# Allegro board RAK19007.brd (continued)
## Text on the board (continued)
User.Comments: 1 | 2 | 3 | 4 | B1 | C1 | G1 | J1 | L1 | N1 | R1 | U1 | W1 | D2 | F2 | H2 | K2 | M2 | P2 | T2 | Y2 | AB2 | AD2 | B3 | AD4 | B5 | AC5 | AD6 | B7 | A8 | AD8 | B9 | AC9 | A10 | AD10 | B11 | AC11 | A12 | AD12 | B13 | DPAD | AC13 | A14 | AD14 | B15 | AC15 | A16 | AD16 | B17 | AC17 | A18 | AD18 | B19 | AC19 | A20 | AD20 | AC21 | A22 | AD22 | A23 | D23 | F23 | H23 | P23 | T23 | V23 | Y23 | AD23 | B24 | E24 | J24 | L24 | N24 | R24 | U24 | W24 | AA24 | AC24 | USB-MC-001-05 | CM212H | PH254-115-04 | 8 | 7 | 9 | 6 | 5
Ref Des/Assembly Top: 4PIN | MICRO_USB_NJZ_MICRO_USB_001_4PI | 32.768K | CM212H_CM212H_32.768K_CM212H | HEADER1X4_PH254-115-04_HEADER1X | Header1X4 | J5 | X1 | J9 | J14 | J15 | J10 | J12 | U10
Ref Des/Silkscreen Top: CPU SLOT | SLOT B | SLOT A | IO SLOT | RESET | SOLAR | BATTERY | RAK19007 Ver.C
BODY_CENTER: OPEN WINDOW | V-cut | 4842.5180 mil | 4409.4460 mil
DIMENSION: SOLDER MASK:BLACK | BOARD NAME: | UNITS:      MILS | SILKSCREEN COLOR: WHITE | DIELECTRIC MATERIAL: FR-4 | PLATED TECHNICS: | SINGLE IMPEDANCE | DIFF IMPEDANCE | SHORT NET NO. | REQUIREMENT. | [Zo] | [0] | RAK19007 VC | 1. ENIG | TG Value:TG150 | L1 L4-6.1MIL/5.1MIL/6.1MIL width impedance 100OHM +/-10% | L1 L4-8MIL/4.5MIL/8MIL width impedance 90OHM +/-10% | LAYERS: | OPEN WINDOWS: | Please mark:UL/94V-0 | SHORT NET POSITION | 4 | Layer Stackup | GND02 | ART03 | FR4(1080+7628) | Art04 | Art01 | CORE | SPELL MODE: | BOARD THICKNESS:   mm+/-10% | Thickness (Mil) | 15 MIL | 1.4MIL | 0.7MIL | 10 MIL | 1 | 0.5+plating | 1.0 | Oz | 1--ARTWORK TOP | 2--ARTWORK GND02 | 3--ARTWORK POWER03 | 4--ARTWORK BOTTOM
DEVICE_TYPE_TOP: ICT_ID_ID-BOARD1_NC | INDUCTOR_SL0603_10UH/NC_MLZ1608 | RESISTOR_SR0603_1M_RC0603JR-071 | INDUCTOR_SL0603_10UH_MLZ1608M10 | CAPACITOR NP_SC0402_100NF_CC040 | CAPACITOR NP_SC0402_4.7UF_CC040 | INDUCTOR_SL0402_3.9NH_LQP15MN3N | RESISTOR_SR0402_NC_RC0402JR-070 | CAPACITOR NP_SC0402_5.6PF_GRM15 | INDUCTOR_SL0402_13NH_LQW15AN13N | CAPACITOR NP_SC0402_12PF_CC0402 | CAPACITOR NP_SC0402_1.0PF_GJM15 | CAPACITOR NP_SC0402_100PF_CC040 | CAPACITOR NP_SC0402_NC_GJM1555C | RESISTOR_SR0402_100K_RC0402JR-0 | RESISTOR_SR0402_4.7K_RC0402JR-0 | CAPACITOR NP_SC0402_NC_CC0402KR | CAPACITOR NP_SC0402_1UF_CC0402K | CAPACITOR NP_SC0402_1NF_CC0402K | RESISTOR_SR0402_0_RC0402JR-070R | CAPACITOR NP_SC0603_47NF_CC0603 | HOLE_MH103CCA_DNP | UFL_SCOXSMA_T_IPEX_L10-03001-01 | LED_SD0603-LED-B_GREEN_19-217/G | CRYSTAL_4P_XRCGB32M000F2P10R0_3
COMPVAL_TYPE_TOP: NC | Solar_conn_2P
User.12: FIGURE | FINISHED_SIZE | 7.874 | 27.56 | 31.0 | 40.0 | 84.0 | 106.0 | 19.685 | 27.559 | 80.0 | 47.244x23.622 | 62.992x23.622 | 74.803x23.622 | ROTATION | - | 90.000 | 0.000 | DRILL CHART: TOP to BOTTOM | ALL UNITS ARE IN MILS | TOLERANCE_DRILL | +0.0/-0.0 | +3.0/-3.0 | +2.0/-2.0 | PLATED | NON-PLATED | QTY | 539 | 2 | 12 | 4
